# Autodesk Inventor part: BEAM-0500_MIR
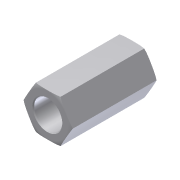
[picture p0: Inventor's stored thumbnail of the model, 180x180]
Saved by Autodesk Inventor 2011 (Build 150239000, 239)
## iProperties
Created: 2008-05
Part Number: BEAM-0500_MIR
Document SubType Name: Modeling
Density: 1 g/cm^3
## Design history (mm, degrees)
derived "BEAM-0500.ipt"
body "Solid1"
tag "TaggingFeature2"
feature "DerivedBody::BEAM-0500.ipt" dims "d0" = 10
